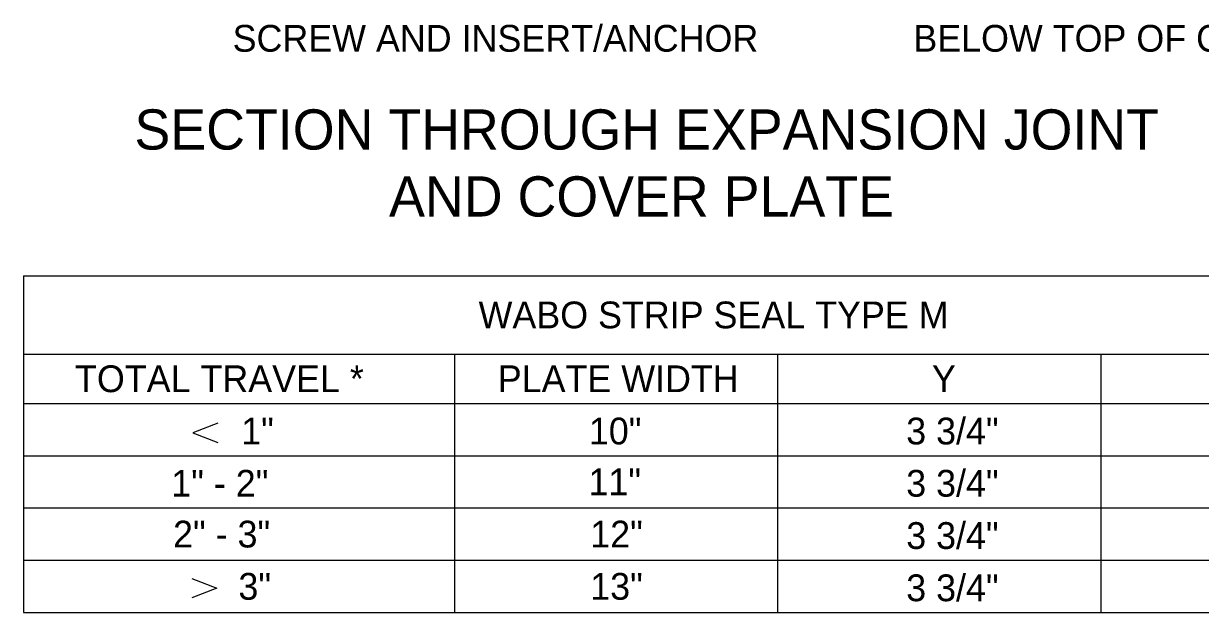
# Model space of a CAD drawing. Extents: x 19590 to 20151, y 19944 to 20103.
# Drawn here: x 19681.91 to 19703.76, y 20050.32 to 20061.26 of the extents above; entities that cross this region are included whole.
import ezdxf

# ---------------------------------------------------------------- set-up
doc = ezdxf.new("R2010")
doc.units = 0
doc.layers.add('DETAIL_TEXT_DIMEN_PR', color=7, linetype='Continuous')
doc.layers.add('Level 1', color=7, linetype='Continuous')

# ---------------------------------------------------------------- blocks, each defined once
blk = doc.blocks.new('TERM')
at = {"layer": 'DETAIL_TEXT_DIMEN_PR'}
for p, q in [((-0.0388, -0.01), (0, 0)), ((0, 0), (-0.0387, 0.01))]:
    blk.add_line(p, q, dxfattribs=at)

msp = doc.modelspace()

# ---------------------------------------------------------------- linework, layer by layer
at = {"layer": 'DETAIL_TEXT_DIMEN_PR'}
for p, q in [((19681.908, 20056.576), (19707.908, 20056.576)), ((19681.908, 20056.576), (19681.908, 20050.319)), ((19681.908, 20056.576), (19707.908, 20056.576)), ((19681.908, 20056.576), (19681.908, 20050.319)), ((19681.917, 20055.119), (19707.908, 20055.119)), ((19681.917, 20055.119), (19707.908, 20055.119)), ((19689.908, 20055.119), (19689.908, 20050.319)), ((19689.908, 20055.119), (19689.908, 20050.319)), ((19695.908, 20055.119), (19695.908, 20050.319)), ((19695.908, 20055.119), (19695.908, 20050.319)), ((19701.908, 20055.119), (19701.908, 20050.319)), ((19701.908, 20055.119), (19701.908, 20050.319)), ((19681.908, 20054.202), (19707.908, 20054.202)), ((19681.908, 20054.202), (19707.908, 20054.202)), ((19681.908, 20053.231), (19707.908, 20053.231)), ((19681.908, 20053.231), (19707.908, 20053.231)), ((19681.908, 20052.26), (19707.908, 20052.26)), ((19681.908, 20052.26), (19707.908, 20052.26)), ((19681.908, 20051.289), (19707.908, 20051.289)), ((19681.908, 20051.289), (19707.908, 20051.289)), ((19681.908, 20050.319), (19707.908, 20050.319)), ((19681.908, 20050.319), (19707.908, 20050.319))]:
    msp.add_line(p, q, dxfattribs=at)

# ---------------------------------------------------------------- block references
at = {"layer": 'Level 1', "xscale": 12, "yscale": 18, "rotation": 180}
msp.add_blockref('TERM', (19685.053, 20053.655), dxfattribs=at)
msp.add_blockref('TERM', (19685.053, 20053.655), dxfattribs=at)
at = {"layer": 'Level 1', "xscale": 12, "yscale": -18}
msp.add_blockref('TERM', (19685.498, 20050.77), dxfattribs=at)
msp.add_blockref('TERM', (19685.498, 20050.77), dxfattribs=at)

# ---------------------------------------------------------------- texts
at = {"layer": 'DETAIL_TEXT_DIMEN_PR'}
for s, height, p in [('SCREW AND INSERT/ANCHOR', 0.49762, (19685.79, 20060.737)), ('SCREW AND INSERT/ANCHOR', 0.49762, (19685.79, 20060.737)), ('BELOW TOP OF CONCRETE', 0.49762, (19698.429, 20060.737)), ('BELOW TOP OF CONCRETE', 0.49762, (19698.429, 20060.737)), ('SECTION THROUGH EXPANSION JOINT', 0.74653, (19683.967, 20058.919)), ('SECTION THROUGH EXPANSION JOINT', 0.74653, (19683.967, 20058.919)), ('AND COVER PLATE', 0.74653, (19688.695, 20057.675)), ('AND COVER PLATE', 0.74653, (19688.695, 20057.675))]:
    msp.add_text(s, height=height, dxfattribs=at).set_placement(p)
for s, height, p in [('WABO STRIP SEAL TYPE M', 0.49762, (19690.357, 20055.598)), ('WABO STRIP SEAL TYPE M', 0.49762, (19690.357, 20055.598)), ('TOTAL TRAVEL *', 0.49762, (19682.864, 20054.412)), ('TOTAL TRAVEL *', 0.49762, (19682.864, 20054.412)), ('PLATE WIDTH', 0.49762, (19690.714, 20054.412)), ('PLATE WIDTH', 0.49762, (19690.714, 20054.412)), ('Y', 0.498, (19698.774, 20054.412)), ('Y', 0.498, (19698.774, 20054.412)), (' 1"', 0.4976, (19685.764, 20053.441)), (' 1"', 0.4976, (19685.764, 20053.441)), ('10"', 0.4976, (19692.405, 20053.441)), ('10"', 0.4976, (19692.405, 20053.441)), ('3 3/4"', 0.4976, (19698.297, 20053.441)), ('3 3/4"', 0.4976, (19698.297, 20053.441)), ('1" - 2"', 0.4976, (19684.651, 20052.47)), ('1" - 2"', 0.4976, (19684.651, 20052.47)), ('11"', 0.4976, (19692.397, 20052.497)), ('11"', 0.4976, (19692.397, 20052.497)), ('3 3/4"', 0.4976, (19698.297, 20052.47)), ('3 3/4"', 0.4976, (19698.297, 20052.47)), ('2" - 3"', 0.4976, (19684.684, 20051.526)), ('2" - 3"', 0.4976, (19684.684, 20051.526)), ('12"', 0.4976, (19692.43, 20051.526)), ('12"', 0.4976, (19692.43, 20051.526)), ('3 3/4"', 0.4976, (19698.297, 20051.499)), ('3 3/4"', 0.4976, (19698.297, 20051.499)), (' 3"', 0.4976, (19685.713, 20050.555)), (' 3"', 0.4976, (19685.713, 20050.555)), ('13"', 0.4976, (19692.43, 20050.555)), ('13"', 0.4976, (19692.43, 20050.555)), ('3 3/4"', 0.4976, (19698.297, 20050.528)), ('3 3/4"', 0.4976, (19698.297, 20050.528))]:
    msp.add_text(s, height=height, rotation=0, dxfattribs=at).set_placement(p)

doc.saveas('drawing.dxf')
